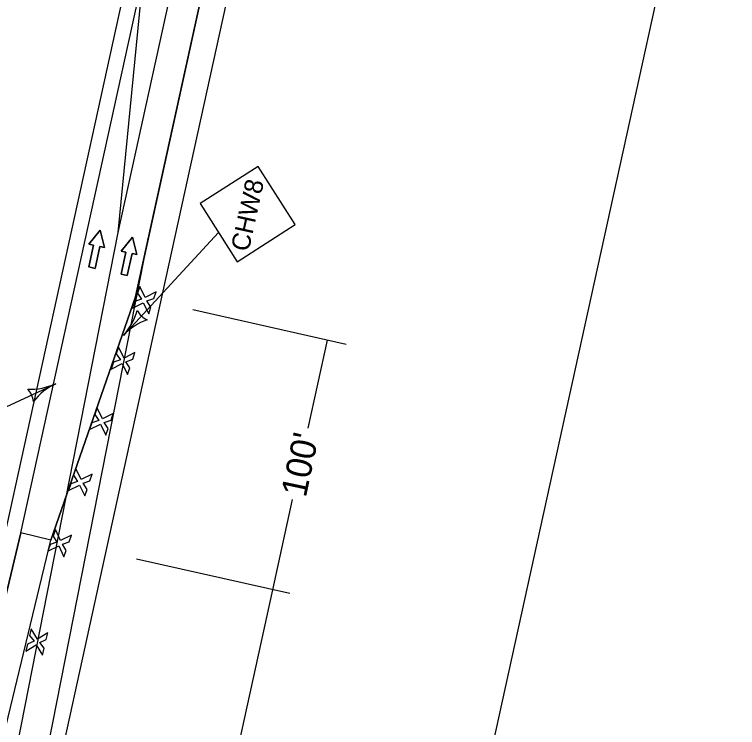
# Model space of a CAD drawing. Extents: x 14104283 to 14121738, y 8635219 to 8671666.
# Drawn here: x 14108149.2 to 14108432.3, y 8640616.4 to 8640895.4 of the extents above; entities that cross this region are included whole.
import ezdxf

# ---------------------------------------------------------------- set-up
doc = ezdxf.new("R2010")
doc.units = 0
for name, color, linetype in [('Cell', 7, 'Continuous'), ('Default', 7, 'Continuous'), ('dsnNonPlotable', 7, 'Continuous'), ('dsnPaintExistingBrokenLaneLineWhite', 7, 'Continuous'), ('dsnPaintExistingEdgeLineRightWhite', 7, 'Continuous'), ('dsnPaintPlaceEdgeLineLeftYellow', 7, 'Continuous'), ('dsnStdLabel', 7, 'Continuous'), ('dsnStgShadingPrevPav', 7, 'Continuous'), ('dsnTapePlaceChannelizingLaneWhite', 7, 'Continuous'), ('dsnTapePlaceChannelizingLaneYellow', 7, 'Continuous'), ('dsnTapeRemoveChannelizingWhite', 7, 'Continuous'), ('dsnTapeRemoveChannelizingYellow', 7, 'Continuous')]:
    doc.layers.add(name, color=color, linetype=linetype)

msp = doc.modelspace()

# ---------------------------------------------------------------- linework, layer by layer
at = {"layer": 'Cell'}
for p, q in [((14108198.23, 8640788.99), (14108197.35, 8640786.39)), ((14108200.35, 8640784.72), (14108198.23, 8640788.99)), ((14108204.62, 8640786.83), (14108200.35, 8640784.72)), ((14108203.74, 8640784.23), (14108204.62, 8640786.83)), ((14108198.92, 8640784.01), (14108196.23, 8640783.07)), ((14108197.35, 8640786.39), (14108198.92, 8640784.01)), ((14108201.05, 8640783.29), (14108203.74, 8640784.23)), ((14108196.23, 8640783.07), (14108195.35, 8640780.47)), ((14108195.35, 8640780.47), (14108199.63, 8640782.58)), ((14108199.63, 8640782.58), (14108201.74, 8640778.31)), ((14108202.62, 8640780.91), (14108201.05, 8640783.29)), ((14108201.74, 8640778.31), (14108202.62, 8640780.91)), ((14108189.93, 8640765.22), (14108189.07, 8640762.61)), ((14108192.08, 8640760.96), (14108189.93, 8640765.22)), ((14108189.07, 8640762.61), (14108190.65, 8640760.24)), ((14108196.34, 8640763.1), (14108192.08, 8640760.96)), ((14108195.48, 8640760.49), (14108196.34, 8640763.1)), ((14108187.97, 8640759.29), (14108187.1, 8640756.68)), ((14108187.1, 8640756.68), (14108191.37, 8640758.82)), ((14108190.65, 8640760.24), (14108187.97, 8640759.29)), ((14108191.37, 8640758.82), (14108193.51, 8640754.55)), ((14108192.79, 8640759.53), (14108195.48, 8640760.49)), ((14108194.37, 8640757.16), (14108192.79, 8640759.53)), ((14108193.51, 8640754.55), (14108194.37, 8640757.16)), ((14108181.51, 8640741.48), (14108180.62, 8640738.87)), ((14108183.62, 8640737.19), (14108181.51, 8640741.48)), ((14108180.62, 8640738.87), (14108182.19, 8640736.49)), ((14108187.9, 8640739.3), (14108183.62, 8640737.19)), ((14108187.01, 8640736.7), (14108187.9, 8640739.3)), ((14108179.5, 8640735.56), (14108178.61, 8640732.96)), ((14108182.19, 8640736.49), (14108179.5, 8640735.56)), ((14108184.32, 8640735.77), (14108187.01, 8640736.7)), ((14108185.89, 8640733.38), (14108184.32, 8640735.77)), ((14108178.61, 8640732.96), (14108182.89, 8640735.06)), ((14108182.89, 8640735.06), (14108185, 8640730.78)), ((14108185, 8640730.78), (14108185.89, 8640733.38)), ((14108173.25, 8640717.69), (14108172.36, 8640715.09)), ((14108175.35, 8640713.4), (14108173.25, 8640717.69)), ((14108172.36, 8640715.09), (14108173.92, 8640712.71)), ((14108179.64, 8640715.5), (14108175.35, 8640713.4)), ((14108176.04, 8640711.97), (14108178.74, 8640712.9)), ((14108178.74, 8640712.9), (14108179.64, 8640715.5)), ((14108171.22, 8640711.78), (14108170.33, 8640709.18)), ((14108170.33, 8640709.18), (14108174.62, 8640711.28)), ((14108173.92, 8640712.71), (14108171.22, 8640711.78)), ((14108174.62, 8640711.28), (14108176.71, 8640706.99)), ((14108177.6, 8640709.59), (14108176.04, 8640711.97)), ((14108176.71, 8640706.99), (14108177.6, 8640709.59)), ((14108165.21, 8640693.86), (14108164.29, 8640691.27)), ((14108167.27, 8640689.56), (14108165.21, 8640693.86)), ((14108164.29, 8640691.27), (14108165.83, 8640688.87)), ((14108171.57, 8640691.61), (14108167.27, 8640689.56)), ((14108170.66, 8640689.02), (14108171.57, 8640691.61)), ((14108163.13, 8640687.97), (14108162.21, 8640685.38)), ((14108162.21, 8640685.38), (14108166.52, 8640687.44)), ((14108165.83, 8640688.87), (14108163.13, 8640687.97)), ((14108166.52, 8640687.44), (14108168.57, 8640683.13)), ((14108167.95, 8640688.12), (14108170.66, 8640689.02)), ((14108169.49, 8640685.72), (14108167.95, 8640688.12)), ((14108168.57, 8640683.13), (14108169.49, 8640685.72)), ((14108155.74, 8640655.06), (14108155.1, 8640652.39)), ((14108158.23, 8640650.98), (14108155.74, 8640655.06)), ((14108162.3, 8640653.47), (14108158.23, 8640650.98)), ((14108161.66, 8640650.8), (14108162.3, 8640653.47)), ((14108155.1, 8640652.39), (14108156.87, 8640650.15)), ((14108159.06, 8640649.63), (14108161.66, 8640650.8)), ((14108154.27, 8640648.98), (14108153.63, 8640646.31)), ((14108153.63, 8640646.31), (14108157.7, 8640648.8)), ((14108156.87, 8640650.15), (14108154.27, 8640648.98)), ((14108157.7, 8640648.8), (14108160.19, 8640644.72)), ((14108160.83, 8640647.4), (14108159.06, 8640649.63)), ((14108160.19, 8640644.72), (14108160.83, 8640647.4))]:
    msp.add_line(p, q, dxfattribs=at)
for points in [[(14108180.75, 8640796.06), (14108178.31, 8640796.6), (14108180.19, 8640805.14), (14108178.36, 8640805.55), (14108182.76, 8640810.98), (14108184.46, 8640804.2), (14108182.63, 8640804.61)], [(14108193.37, 8640793.29), (14108190.92, 8640793.83), (14108192.81, 8640802.37), (14108190.98, 8640802.78), (14108195.38, 8640808.21), (14108197.08, 8640801.43), (14108195.25, 8640801.83)]]:
    msp.add_lwpolyline(points, close=True, dxfattribs=at)
for points in [[(14108182.63, 8640804.61), (14108184.46, 8640804.2), (14108182.76, 8640810.98), (14108178.36, 8640805.55), (14108180.19, 8640805.14), (14108178.31, 8640796.6), (14108180.75, 8640796.06), (14108182.63, 8640804.61)], [(14108195.25, 8640801.83), (14108197.08, 8640801.43), (14108195.38, 8640808.21), (14108190.98, 8640802.78), (14108192.81, 8640802.37), (14108190.92, 8640793.83), (14108193.37, 8640793.29), (14108195.25, 8640801.83)]]:
    msp.add_lwpolyline(points, dxfattribs=at)
at = {"layer": 'Default'}
for p, q in [((14108723.98, 8643185.75), (14108196.58, 8640784.95)), ((14108151.72, 8640692.57), (14108294.65, 8641343.23)), ((14108196.58, 8640784.95), (14108163.38, 8640689.76)), ((14108151.72, 8640692.57), (14108081.5, 8640400.87)), ((14108163.38, 8640689.76), (14108151.72, 8640692.57)), ((14108163.38, 8640689.76), (14108151.72, 8640692.57)), ((14108093.19, 8640398.18), (14108163.38, 8640689.76))]:
    msp.add_line(p, q, dxfattribs=at)
at = {"layer": 'dsnNonPlotable'}
msp.add_lwpolyline([(14107651.31, 8639844.94), (14107987.7, 8641375.92), (14108480.93, 8641267.54), (14108144.54, 8639736.56)], close=True, dxfattribs=at)
at = {"layer": 'dsnPaintExistingBrokenLaneLineWhite'}
msp.add_line((14108189.82, 8640810.08), (14108306.37, 8641340.66), dxfattribs=at)
at = {"layer": 'dsnPaintExistingEdgeLineRightWhite'}
for p, q in [((14108201.57, 8640807.63), (14108723.98, 8643185.75)), ((14108196.58, 8640784.95), (14108201.57, 8640807.63))]:
    msp.add_line(p, q, dxfattribs=at)
at = {"layer": 'dsnPaintPlaceEdgeLineLeftYellow'}
msp.add_line((14108151.72, 8640692.57), (14108199.55, 8640910.32), dxfattribs=at)
at = {"layer": 'dsnStdLabel'}
for p, q in [((14108229.11, 8640810.06), (14108191.85, 8640769.83)), ((14108279.03, 8640766.32), (14108219.06, 8640779.87)), ((14108264.25, 8640733.54), (14108271.81, 8640767.95)), ((14108138.22, 8640738.34), (14108165.33, 8640750.93)), ((14108250.34, 8640670.22), (14108258.11, 8640705.58)), ((14108256.99, 8640668.78), (14108197.02, 8640682.33)), ((14108185.98, 8640377.23), (14108250.34, 8640670.22))]:
    msp.add_line(p, q, dxfattribs=at)
msp.add_lwpolyline([(14108236.39, 8640798.68), (14108259.13, 8640813.23), (14108244.58, 8640835.98), (14108221.84, 8640821.43)], close=True, dxfattribs=at)
for centre, radius, start, end in [((14108175.02, 8640785.42), 22.95, 317.1934, 345.2647), ((14108204.93, 8640783.95), 8.86, 209.4593, 244.9277), ((14108208.69, 8640754.24), 22.95, 109.1223, 137.1936), ((14108155.66, 8640771.74), 22.95, 266.8399, 294.9112), ((14108175, 8640730.11), 22.95, 114.9111, 142.9824), ((14108147.88, 8640742.82), 8.86, 7.1769, 42.6454)]:
    msp.add_arc(centre, radius, start, end, dxfattribs=at)
at = {"layer": 'dsnStgShadingPrevPav'}
msp.add_lwpolyline([(14108081.5, 8640400.87), (14108123.34, 8640591.33), (14108126.55, 8640605.98), (14108216.67, 8641016.2), (14108268.16, 8641250.61), (14108382.95, 8641773.15), (14108422.02, 8641764.57), (14108309.38, 8641251.8), (14108270.22, 8641073.55), (14108265.93, 8641054.01), (14108255.74, 8641007.62), (14108202.1, 8640763.44), (14108120.56, 8640392.29)], close=True, dxfattribs=at)
at = {"layer": 'dsnTapePlaceChannelizingLaneWhite'}
for p, q in [((14108163.38, 8640689.76), (14108196.58, 8640784.95)), ((14108093.19, 8640398.18), (14108163.38, 8640689.76))]:
    msp.add_line(p, q, dxfattribs=at)
at = {"layer": 'dsnTapePlaceChannelizingLaneYellow'}
msp.add_line((14108081.5, 8640400.87), (14108151.72, 8640692.57), dxfattribs=at)
at = {"layer": 'dsnTapeRemoveChannelizingWhite'}
msp.add_line((14108143.57, 8640513.35), (14108201.59, 8640807.75), dxfattribs=at)
at = {"layer": 'dsnTapeRemoveChannelizingYellow'}
for p, q in [((14108189.82, 8640810.08), (14108199.55, 8640910.32)), ((14108131.8, 8640515.67), (14108189.82, 8640810.08))]:
    msp.add_line(p, q, dxfattribs=at)

# ---------------------------------------------------------------- texts
at = {"layer": 'dsnStdLabel'}
for s, height, rotation, p in [('CHW8', 7.2, 77.6078, (14108240.87, 8640802.31)), ("100'", 10, 78.0531, (14108263.27, 8640706.11))]:
    msp.add_text(s, height=height, rotation=rotation, dxfattribs=at).set_placement(p)

doc.saveas('drawing.dxf')
